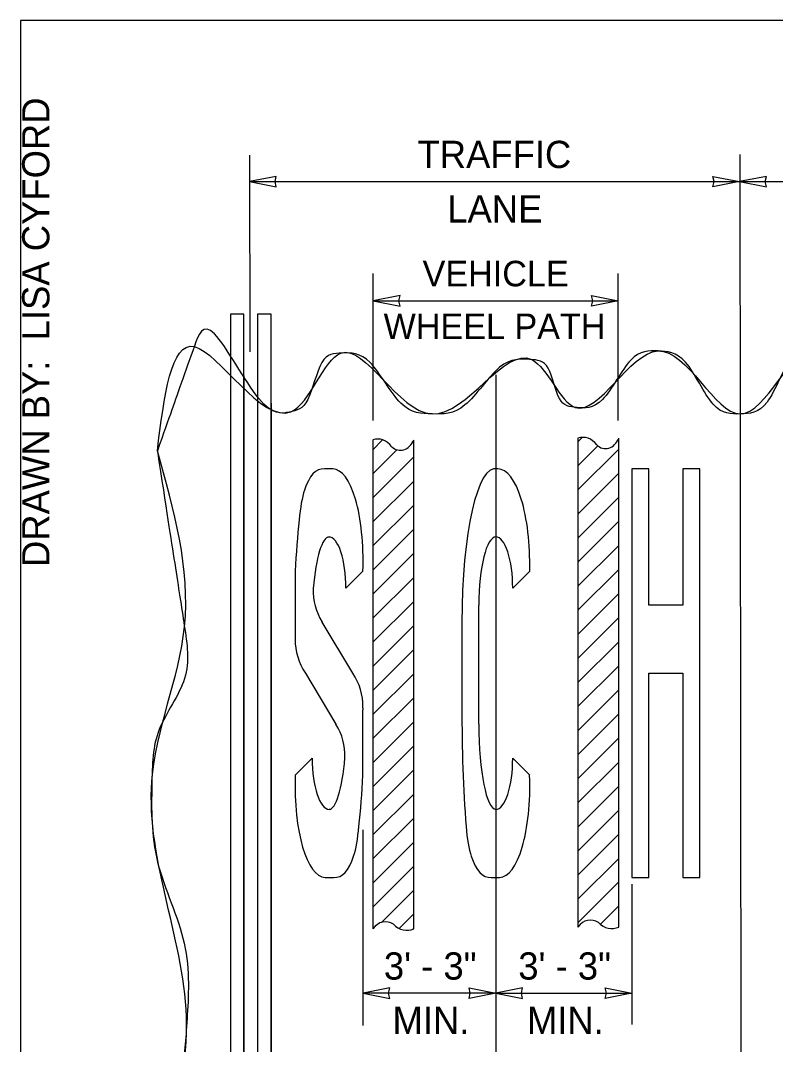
# Model space of a CAD drawing. Extents: x 99862 to 103151, y 100000 to 105076.
# Drawn here: x 99862 to 100306, y 104474 to 105076 of the extents above; entities that cross this region are included whole.
import ezdxf

# ---------------------------------------------------------------- set-up
doc = ezdxf.new("R2010")
doc.units = 0
for name, color, linetype in [('Level 1', 7, 'Continuous'), ('Level 15', 7, 'Continuous'), ('Level 2', 7, 'Continuous'), ('Level 20', 7, 'Continuous'), ('Level 3', 7, 'Continuous'), ('Level 6', 7, 'Continuous'), ('Level 62', 7, 'Continuous'), ('Level 8', 7, 'Continuous')]:
    doc.layers.add(name, color=color, linetype=linetype)

msp = doc.modelspace()

# ---------------------------------------------------------------- linework, layer by layer
at = {"layer": 'Level 1'}
msp.add_lwpolyline([(99862, 102999.5), (103151, 102999.5), (103151, 105075.5), (99862, 105075.5)], close=True, dxfattribs=at)
at = {"layer": 'Level 15'}
for p, q in [((99996.64, 104996.33), (99996.73, 104880.89)), ((100284.74, 104996.68), (100285.42, 104465.76)), ((99996.63, 104980.83), (100284.63, 104980.83)), ((100284.63, 104980.83), (100575.36, 104980.83)), ((100069.36, 104840.62), (100069.36, 104926.83)), ((100213.36, 104840.62), (100213.36, 104926.83)), ((100069.36, 104910.83), (100213.36, 104910.83)), ((100141.36, 104867.44), (100141.36, 104420.8)), ((100063.35, 104485.11), (100063.35, 104600.11)), ((100221.36, 104568.11), (100221.36, 104485.77)), ((100141.36, 104504.11), (100063.36, 104504.11)), ((100141.36, 104504.11), (100221.36, 104504.11))]:
    msp.add_line(p, q, dxfattribs=at)
for points in [[(99996.63, 104980.83), (100012.36, 104977.75), (100011.63, 104980.83), (100012.36, 104983.92)], [(100284.63, 104980.83), (100268.91, 104977.75), (100269.63, 104980.83), (100268.91, 104983.92)], [(100284.63, 104980.83), (100300.36, 104977.75), (100299.63, 104980.83), (100300.36, 104983.92)], [(100069.36, 104910.83), (100085.08, 104907.75), (100084.36, 104910.83), (100085.08, 104913.92)], [(100213.36, 104910.83), (100197.63, 104907.75), (100198.36, 104910.83), (100197.63, 104913.92)], [(100063.36, 104504.11), (100079.08, 104501.02), (100078.36, 104504.11), (100079.08, 104507.19)], [(100141.36, 104504.11), (100125.63, 104501.02), (100126.36, 104504.11), (100125.63, 104507.19)], [(100141.36, 104504.11), (100157.08, 104501.02), (100156.36, 104504.11), (100157.08, 104507.19)], [(100221.36, 104504.11), (100205.63, 104501.02), (100206.36, 104504.11), (100205.63, 104507.19)]]:
    msp.add_lwpolyline(points, close=True, dxfattribs=at)
msp.add_ellipse((100085.33, 104834.45), major_axis=(0, -11.44), ratio=0.772892, start_param=5.65539, end_param=7.364579, dxfattribs=at)
at = {"layer": 'Level 2'}
msp.add_line((99993.36, 104902.92), (99985.36, 104902.92), dxfattribs=at)
for points in [[(99993.36, 104902.92), (99985.36, 104902.92), (99985.36, 104199.62)], [(99993.36, 104199.62), (99993.36, 104902.92)], [(100001.36, 104902.92), (100001.36, 104242.02)], [(100009.36, 104199.62), (100009.36, 104902.92), (100001.36, 104902.92)], [(100009.36, 104902.92), (100001.36, 104902.92), (100001.36, 104199.62)], [(100009.36, 104199.62), (100009.36, 104902.92)]]:
    msp.add_lwpolyline(points, dxfattribs=at)
at = {"layer": 'Level 3'}
for points in [[(99942.44, 104822.69), (99964.13, 104883.94), (100020.92, 104845.66), (100050.27, 104880.11), (100103.86, 104844.38), (100162.56, 104876.28), (100188.09, 104848.21), (100236.58, 104881.39), (100285.07, 104844.38), (100331.01, 104885.22), (100389.7, 104848.21), (100426.71, 104880.11), (100467.55, 104854.59), (100526.24, 104892.87), (100550.49, 104859.7), (100572.63, 104865.98)], [(99944.34, 104403.9), (99959.67, 104485.81), (99939.25, 104628.73), (99958.39, 104719.33), (99942.44, 104822.69)]]:
    msp.add_spline(points, degree=3, dxfattribs=at)
for points in [[(100572.63, 104862.08), (100565.49, 104860.05), (100558.06, 104859.05), (100550.49, 104859.7), (100541.57, 104862.25), (100537.59, 104891.99), (100526.24, 104892.87), (100506.89, 104894.37), (100487.29, 104853.94), (100467.55, 104854.59), (100453.98, 104855.04), (100440.17, 104880.64), (100426.71, 104880.11), (100413.05, 104879.58), (100402.73, 104849.24), (100389.7, 104848.21), (100371.2, 104846.74), (100349.09, 104886.25), (100331.01, 104885.22), (100314.99, 104884.3), (100301.12, 104844.83), (100285.07, 104844.38), (100269.13, 104843.94), (100252.89, 104880.81), (100236.58, 104881.39), (100220.87, 104881.95), (100203.86, 104846.74), (100188.09, 104848.21), (100177.9, 104849.16), (100173.07, 104875.52), (100162.56, 104876.28), (100144.07, 104877.63), (100122.88, 104843.97), (100103.86, 104844.38), (100085.53, 104844.78), (100067.33, 104880.6), (100050.27, 104880.11), (100038.28, 104879.77), (100031.44, 104847.84), (100020.92, 104845.66), (100005, 104842.36), (99971.76, 104905.46), (99964.13, 104883.94), (99956.9, 104863.52), (99949.67, 104843.11), (99942.44, 104822.69)], [(99942.44, 104822.69), (99947.76, 104788.24), (99953.08, 104753.78), (99958.39, 104719.33), (99963.1, 104688.82), (99939.78, 104659.21), (99939.25, 104628.73), (99938.42, 104581.21), (99962.79, 104533.38), (99959.67, 104485.81), (99957.87, 104458.39), (99949.78, 104431.25), (99944.34, 104403.9)]]:
    msp.add_open_spline(points, degree=3, dxfattribs=at)
at = {"layer": 'Level 6'}
for p, q in [((100069.13, 104823.38), (100074.83, 104829.08)), ((100189.63, 104828.02), (100192.11, 104830.5)), ((100069.13, 104809.23), (100083.23, 104823.34)), ((100189.63, 104813.88), (100201.35, 104825.6)), ((100189.63, 104799.73), (100213.63, 104823.73)), ((100069.13, 104795.09), (100093.13, 104819.09)), ((100069.13, 104780.95), (100093.13, 104804.95)), ((100189.63, 104785.59), (100213.63, 104809.59)), ((100189.63, 104771.45), (100213.63, 104795.45)), ((100069.13, 104766.81), (100093.13, 104790.81)), ((100189.63, 104757.31), (100213.63, 104781.31)), ((100069.13, 104752.67), (100093.13, 104776.67)), ((100069.13, 104738.52), (100093.13, 104762.52)), ((100189.63, 104743.16), (100213.63, 104767.16)), ((100189.63, 104729.02), (100213.63, 104753.02)), ((100069.13, 104724.38), (100093.13, 104748.38)), ((100189.63, 104714.88), (100213.63, 104738.88)), ((100069.13, 104710.24), (100093.13, 104734.24)), ((100189.63, 104700.74), (100213.63, 104724.74)), ((100069.13, 104696.1), (100093.13, 104720.1)), ((100189.63, 104686.6), (100213.63, 104710.6)), ((100069.13, 104681.96), (100093.13, 104705.96)), ((100189.63, 104672.45), (100213.63, 104696.45)), ((100069.13, 104667.81), (100093.13, 104691.81)), ((100189.63, 104658.31), (100213.63, 104682.31)), ((100069.13, 104653.67), (100093.13, 104677.67)), ((100189.63, 104644.17), (100213.63, 104668.17)), ((100069.13, 104639.53), (100093.13, 104663.53)), ((100069.13, 104625.39), (100093.13, 104649.39)), ((100189.63, 104630.03), (100213.63, 104654.03)), ((100189.63, 104615.89), (100213.63, 104639.89)), ((100069.13, 104611.24), (100093.13, 104635.24)), ((100189.63, 104601.74), (100213.63, 104625.74)), ((100069.13, 104597.1), (100093.13, 104621.1)), ((100069.13, 104582.96), (100093.13, 104606.96)), ((100189.63, 104587.6), (100213.63, 104611.6)), ((100189.63, 104573.46), (100213.63, 104597.46)), ((100069.13, 104568.82), (100093.13, 104592.82)), ((100189.63, 104559.32), (100213.63, 104583.32)), ((100069.13, 104554.68), (100093.13, 104578.68)), ((100074.1, 104545.65), (100093.13, 104564.68)), ((100190.04, 104545.85), (100213.51, 104569.32)), ((100202.74, 104544.56), (100213.27, 104555.09)), ((100084.39, 104541.94), (100093.13, 104550.68)), ((100092.76, 104541.86), (100093.13, 104542.23))]:
    msp.add_line(p, q, dxfattribs=at)
for points in [[(99985.36, 104876.17), (99985.36, 104227.04)], [(99993.43, 104237.26), (99993.43, 104866.84)], [(100001.36, 104858.39), (100001.36, 104242.24)], [(100009.59, 104242.77), (100009.59, 104850.64)], [(100069.13, 104829.07), (100069.13, 104542)], [(100093.13, 104542), (100093.13, 104829.07)], [(100189.63, 104830.07), (100189.63, 104543)], [(100213.63, 104543), (100213.63, 104830.07)]]:
    msp.add_lwpolyline(points, dxfattribs=at)
for centre, major_axis, start_param, end_param in [((100072.13, 104815.27), (0, -14.34), 2.334921, 3.41576), ((100085.33, 104834.45), (0, -11.44), 5.65539, 7.364579), ((100192.63, 104816.27), (0, -14.34), 2.334921, 3.41576), ((100205.83, 104835.45), (0, -11.44), 5.65539, 7.364579), ((100076.47, 104532.94), (0, -13.12), 2.66324, 3.950242), ((100196.97, 104533.94), (0, -13.12), 2.66324, 3.950242), ((100088.97, 104557.52), (0, -16.44), 5.61869, 6.617383), ((100209.47, 104558.52), (0, -16.44), 5.61869, 6.617383)]:
    msp.add_ellipse(centre, major_axis=major_axis, ratio=0.772892, start_param=start_param, end_param=end_param, dxfattribs=at)
at = {"layer": 'Level 8'}
for p, q in [((100045.54, 104812.09), (100040.61, 104812.09)), ((100142.59, 104812.11), (100139.95, 104812.11)), ((100231.36, 104812.11), (100221.36, 104812.11)), ((100221.36, 104812.11), (100221.36, 104572.11)), ((100231.36, 104732.11), (100231.36, 104812.11)), ((100261.36, 104812.11), (100251.36, 104812.11)), ((100251.36, 104812.11), (100251.36, 104732.11)), ((100261.36, 104572.11), (100261.36, 104812.11)), ((100023.41, 104752.11), (100023.41, 104714.8)), ((100053.28, 104742.09), (100063.25, 104752.09)), ((100151.3, 104742.11), (100161.26, 104752.11)), ((100131.39, 104662.12), (100131.39, 104732.11)), ((100251.36, 104732.11), (100231.36, 104732.11)), ((100057.32, 104692.11), (100039.37, 104722.16)), ((100121.43, 104712.11), (100121.43, 104672.12)), ((100029.45, 104692.11), (100047.34, 104662.11)), ((100231.36, 104572.11), (100231.36, 104692.11)), ((100231.36, 104692.11), (100251.36, 104692.11)), ((100251.36, 104692.11), (100251.36, 104572.11)), ((100063.3, 104632.11), (100063.3, 104670.23)), ((100033.43, 104642.12), (100023.46, 104632.12)), ((100161.26, 104632.12), (100151.3, 104642.12)), ((100041.17, 104572.12), (100046.1, 104572.12)), ((100138.65, 104572.12), (100143.58, 104572.12)), ((100221.36, 104572.11), (100231.36, 104572.11)), ((100251.36, 104572.11), (100261.36, 104572.11))]:
    msp.add_line(p, q, dxfattribs=at)
for points in [[(100045.54, 104812.09), (100040.61, 104812.09)], [(100045.54, 104812.09), (100040.61, 104812.09)], [(100142.59, 104812.11), (100139.95, 104812.11)], [(100142.59, 104812.11), (100139.95, 104812.11)], [(100251.36, 104812.11), (100251.36, 104732.11), (100231.36, 104732.11), (100231.36, 104812.11), (100221.36, 104812.11), (100221.36, 104572.11), (100231.36, 104572.11), (100231.36, 104692.11), (100251.36, 104692.11), (100251.36, 104572.11), (100261.36, 104572.11), (100261.36, 104812.11), (100251.36, 104812.11)], [(100251.36, 104572.11), (100261.36, 104572.11), (100261.36, 104812.11), (100251.36, 104812.11), (100251.36, 104732.11), (100231.36, 104732.11), (100231.36, 104812.11), (100221.36, 104812.11), (100221.36, 104572.11), (100231.36, 104572.11), (100231.36, 104692.11), (100251.36, 104692.11), (100251.36, 104572.11)], [(100023.41, 104752.11), (100023.41, 104714.8)], [(100023.41, 104752.11), (100023.41, 104714.8)], [(100053.28, 104742.09), (100063.25, 104752.09)], [(100053.28, 104742.09), (100063.25, 104752.09)], [(100151.3, 104742.11), (100161.26, 104752.11)], [(100151.3, 104742.11), (100161.26, 104752.11)], [(100131.39, 104662.12), (100131.39, 104732.11)], [(100131.39, 104662.12), (100131.39, 104732.11)], [(100057.32, 104692.11), (100039.37, 104722.16)], [(100057.32, 104692.11), (100039.37, 104722.16)], [(100121.43, 104712.11), (100121.43, 104672.12)], [(100121.43, 104712.11), (100121.43, 104672.12)], [(100029.45, 104692.11), (100047.34, 104662.11)], [(100029.45, 104692.11), (100047.34, 104662.11)], [(100063.3, 104632.11), (100063.3, 104670.23)], [(100063.3, 104632.11), (100063.3, 104670.23)], [(100033.43, 104642.12), (100023.46, 104632.12)], [(100033.43, 104642.12), (100023.46, 104632.12)], [(100161.26, 104632.12), (100151.3, 104642.12)], [(100161.26, 104632.12), (100151.3, 104642.12)], [(100041.17, 104572.12), (100046.1, 104572.12)], [(100041.17, 104572.12), (100046.1, 104572.12)], [(100138.65, 104572.12), (100143.58, 104572.12)], [(100138.65, 104572.12), (100143.58, 104572.12)]]:
    msp.add_lwpolyline(points, dxfattribs=at)
for centre, major_axis, ratio, start_param, end_param in [((100064.19, 104690.41), (25.63, -121.53), 0.2446, 3.074507, 3.547554), ((100064.19, 104690.41), (25.63, -121.53), 0.2446, 3.074507, 3.547554), ((100043.52, 104752.64), (-2.06, -59.45), 0.331749, 1.573059, 3.143856), ((100043.52, 104752.64), (-2.06, -59.45), 0.331749, 1.573059, 3.143856), ((100141.68, 104716.14), (0.93, -96.05), 0.211336, 3.181491, 4.752287), ((100141.68, 104716.14), (0.93, -96.05), 0.211336, 3.181491, 4.752287), ((100141.31, 104752.44), (-1.32, -59.67), 0.334281, 1.57277, 3.143567), ((100141.31, 104752.44), (-1.32, -59.67), 0.334281, 1.57277, 3.143567), ((100037.56, 104752.04), (3.77, -53.77), 0.217125, 3.612405, 4.10427), ((100037.56, 104752.04), (3.77, -53.77), 0.217125, 3.612405, 4.10427), ((100059.62, 104697.02), (3.11, -171.44), 0.217108, 4.189191, 4.381308), ((100059.62, 104697.02), (3.11, -171.44), 0.217108, 4.189191, 4.381308), ((100043.12, 104722.05), (-0.18, -50.04), 0.199472, 3.141589, 4.305776), ((100043.12, 104722.05), (-0.18, -50.04), 0.199472, 3.141589, 4.305776), ((100043.3, 104742.09), (0, -30), 0.332454, 1.570796, 3.141593), ((100043.3, 104742.09), (0, -30), 0.332454, 1.570796, 3.141593), ((100141.35, 104732.11), (0, -40), 0.248912, 3.141593, 4.712389), ((100141.35, 104732.11), (0, -40), 0.248912, 3.141593, 4.712389), ((100141.35, 104742.11), (0, -30), 0.331883, 1.570796, 3.141593), ((100141.35, 104742.11), (0, -30), 0.331883, 1.570796, 3.141593), ((100133.6, 104758.41), (-98.42, -26.88), 0.570595, 6.105691, 6.458417), ((100133.6, 104758.41), (-98.42, -26.88), 0.570595, 6.105691, 6.458417), ((100124.3, 104731.63), (-99.37, -29.97), 0.583127, 6.109834, 6.456762), ((100124.3, 104731.63), (-99.37, -29.97), 0.583127, 6.109834, 6.456762), ((99964.14, 104653.18), (-97.66, -29.46), 0.583127, 2.963878, 3.316684), ((99964.14, 104653.18), (-97.66, -29.46), 0.583127, 2.963878, 3.316684), ((100173.93, 104719.62), (-11.65, -236.2), 0.216739, 4.925571, 5.243712), ((100173.93, 104719.62), (-11.65, -236.2), 0.216739, 4.925571, 5.243712), ((99953.11, 104625.85), (-98.42, -26.88), 0.570595, 2.964099, 3.316825), ((99953.11, 104625.85), (-98.42, -26.88), 0.570595, 2.964099, 3.316825), ((100141.35, 104662.12), (0, -50), 0.19913, 4.712389, 6.283185), ((100141.35, 104662.12), (0, -50), 0.19913, 4.712389, 6.283185), ((100043.58, 104662.17), (-0.18, -50.04), 0.199472, 6.283181, 7.448473), ((100043.58, 104662.17), (-0.18, -50.04), 0.199472, 6.283181, 7.448473), ((100043.4, 104642.12), (0, -30), 0.332454, 4.712389, 6.283185), ((100043.4, 104642.12), (0, -30), 0.332454, 4.712389, 6.283185), ((100141.35, 104642.12), (0, -30), 0.331883, 6.283185, 7.853982), ((100141.35, 104642.12), (0, -30), 0.331883, 6.283185, 7.853982), ((100043.18, 104631.57), (-2.06, -59.45), 0.331749, 4.714652, 6.285448), ((100043.18, 104631.57), (-2.06, -59.45), 0.331749, 4.714652, 6.285448), ((100027.46, 104686.33), (3.04, -169.67), 0.217108, 1.047598, 1.241649), ((100027.46, 104686.33), (3.04, -169.67), 0.217108, 1.047598, 1.241649), ((100141.56, 104631.57), (2.05, -59.45), 0.331181, 6.280966, 7.851763), ((100141.56, 104631.57), (2.05, -59.45), 0.331181, 6.280966, 7.851763), ((100049.15, 104632.17), (3.77, -53.77), 0.217125, 0.470812, 0.962677), ((100049.15, 104632.17), (3.77, -53.77), 0.217125, 0.470812, 0.962677), ((100135.61, 104632.17), (-3.76, -53.77), 0.216756, 5.320454, 5.812319), ((100135.61, 104632.17), (-3.76, -53.77), 0.216756, 5.320454, 5.812319), ((100022.52, 104693.8), (25.63, -121.53), 0.2446, 6.216099, 6.689147), ((100022.52, 104693.8), (25.63, -121.53), 0.2446, 6.216099, 6.689147), ((100162.19, 104693.79), (-25.58, -121.53), 0.244216, 5.877043, 6.350091), ((100162.19, 104693.79), (-25.58, -121.53), 0.244216, 5.877043, 6.350091)]:
    msp.add_ellipse(centre, major_axis=major_axis, ratio=ratio, start_param=start_param, end_param=end_param, dxfattribs=at)
for points in [[(100023.41, 104714.8), (100023.4, 104713.91), (100023.39, 104713.01), (100023.41, 104712.11)], [(100023.41, 104714.8), (100023.4, 104714.41), (100023.4, 104714.02), (100023.4, 104713.62)], [(100023.4, 104713.62), (100023.4, 104713.12), (100023.4, 104712.61), (100023.41, 104712.11)], [(100063.3, 104670.23), (100063.31, 104670.86), (100063.31, 104671.48), (100063.3, 104672.11)], [(100063.3, 104670.23), (100063.31, 104670.86), (100063.31, 104671.48), (100063.3, 104672.11)]]:
    msp.add_open_spline(points, degree=2, dxfattribs=at)

# ---------------------------------------------------------------- texts
at = {"layer": 'Level 20'}
for s, height, p in [('TRAFFIC', 16, (100095.36, 104988.83)), ('LANE', 16, (100112.85, 104956.83)), ('VEHICLE', 15, (100098.34, 104919.33)), ('WHEEL PATH', 15, (100075.42, 104888.33)), ('3\' - 3"', 16, (100075.57, 104512.11)), ('3\' - 3"', 16, (100154.57, 104512.11)), ('MIN.', 16, (100080.64, 104480.11)), ('MIN.', 16, (100159.64, 104480.11))]:
    msp.add_text(s, height=height, rotation=360, dxfattribs=at).set_placement(p)
at = {"layer": 'Level 62'}
msp.add_text('DRAWN BY:  LISA CYFORD', height=16, rotation=90, dxfattribs=at).set_placement((99879, 104754.47))

doc.saveas('drawing.dxf')
